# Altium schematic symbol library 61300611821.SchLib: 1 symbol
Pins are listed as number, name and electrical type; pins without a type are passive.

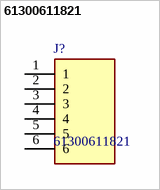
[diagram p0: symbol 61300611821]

## 61300611821
designator J?
WURTH ELEKTRONIK - 61300611821 - PCB Receptacle, Board-to-Board, 2.54 mm, 1 Rows, 6 Contacts, Through Hole, WR-PHD Series; Geometry.Height: 8.65mm
footprint RHDR6W97P0X254_1X6_1574X250X865P
pins: 1, 2, 3, 4, 5, 6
